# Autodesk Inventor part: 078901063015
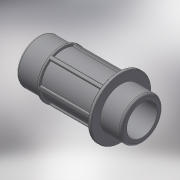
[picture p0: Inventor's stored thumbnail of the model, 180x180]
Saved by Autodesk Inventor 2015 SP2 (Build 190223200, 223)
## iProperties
Created: 2018-02
Part Number: 078901063015
Material: Generic
Description: PLASSON THREADED MALE ADAPTOR 63-1.1/2"
Document SubType Name: Modeling
Designer: KIM
Density: 1 g/cm^3
Appearance: Default
Author: KIM
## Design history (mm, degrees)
derived "078901.ipt"
feature "Solid1::078901.ipt"
tag "TaggingFeature1"
body "Solid1"
other parameters: "d4" = 2.39015, "d14" = 3.82424, "d15" = 1.91212, "d17" = 0, "d20" = 360 deg, "d40" = 22, "d41" = 47.803, "d45" = 52.5833, "d46" = 33.4621, "d47" = 2.2, "d77" = 111, "d78" = 63, "d85" = 0.47803, "d91" = 22.2, "d103" = 25.53, "d104" = 83, "d105" = 0.47803, "R_" = 47.803, "E_" = 83, "l_2" = 22, "l_" = 111, "d_" = 63
